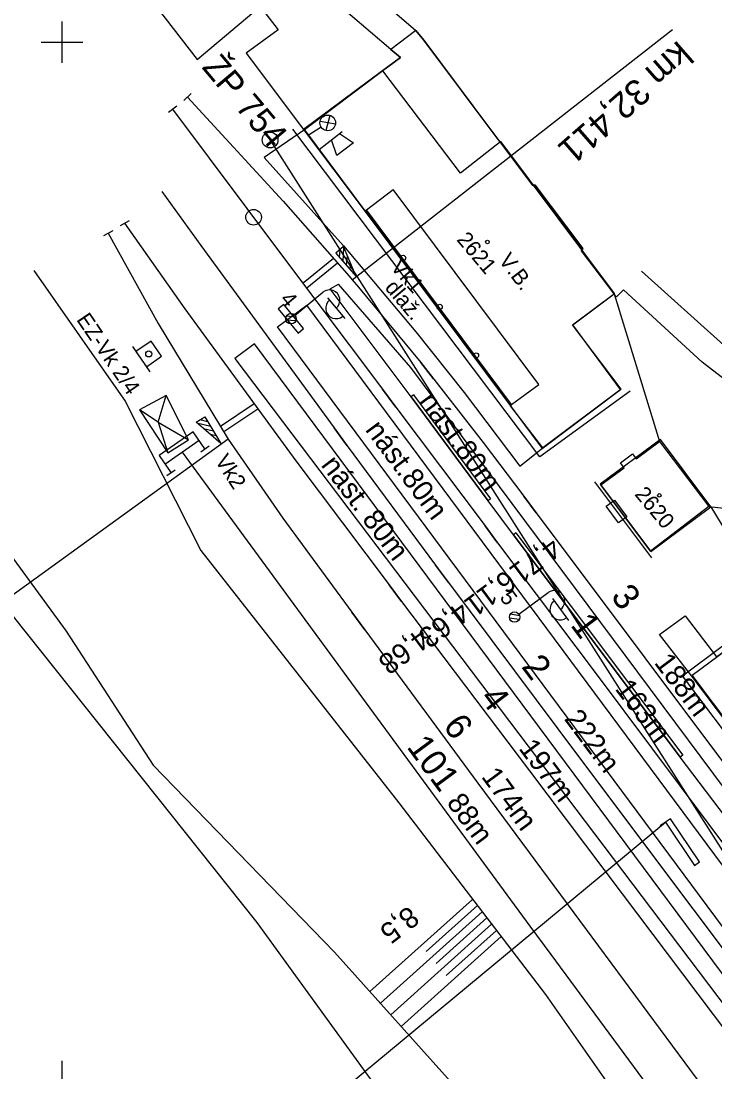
# Model space of a CAD drawing. Extents: x -804166 to -803706, y -1151030 to -1150147.
# Drawn here: x -804103.9 to -804037.2, y -1150299.1 to -1150198 of the extents above; entities that cross this region are included whole.
import ezdxf

# ---------------------------------------------------------------- set-up
doc = ezdxf.new("R2010")
doc.units = 0
for name, color, linetype in [('0381KM032-037P - Vrstva 1', 7, 'Continuous'), ('0381KM032-037P - Vrstva 12', 7, 'Continuous'), ('0381KM032-037P - Vrstva 14', 7, 'Continuous'), ('0381KM032-037P - Vrstva 15', 7, 'Continuous'), ('0381KM032-037P - Vrstva 16', 7, 'Continuous'), ('0381KM032-037P - Vrstva 2', 7, 'Continuous'), ('0381KM032-037P - Vrstva 23', 7, 'Continuous'), ('0381KM032-037P - Vrstva 25', 7, 'Continuous'), ('0381KM032-037P - Vrstva 3', 7, 'Continuous'), ('0381KM032-037P - Vrstva 33', 7, 'Continuous'), ('0381KM032-037P - Vrstva 4', 7, 'Continuous'), ('0381KM032-037P - Vrstva 48', 7, 'Continuous'), ('0381KM032-037P - Vrstva 49', 7, 'Continuous'), ('0381KM032-037P - Vrstva 51', 7, 'Continuous'), ('0381KM032-037P - Vrstva 55', 7, 'Continuous'), ('0381KM032-037P - Vrstva 57', 7, 'Continuous'), ('0381KM032-037P - Vrstva 59', 7, 'Continuous'), ('0381KM032-037P - Vrstva 7', 7, 'Continuous'), ('0381KM032-037P - Vrstva 9', 7, 'Continuous'), ('hran DP - hran DP', 7, 'Continuous'), ('krizky_1000 - Vrstva 1', 7, 'Continuous'), ('vyt_sit - polygon', 7, 'Continuous'), ('vyt_sit - stávající', 7, 'Continuous')]:
    doc.layers.add(name, color=color, linetype=linetype)

msp = doc.modelspace()

# ---------------------------------------------------------------- linework, layer by layer
at = {"layer": '0381KM032-037P - Vrstva 1'}
for points in [[(-804087.93, -1150205.28), (-804078.71, -1150215.28), (-804072.37, -1150222.52), (-804072.08, -1150222.85), (-804071.47, -1150223.58), (-804065.48, -1150230.82), (-804059.47, -1150238.51), (-804055.55, -1150243.68), (-804054.36, -1150245.27), (-804043.89, -1150259.22), (-804035.37, -1150270.61), (-804034.4, -1150271.93), (-804017.97, -1150293.92), (-804002.6, -1150314.46), (-803985.38, -1150337.43), (-803955.87, -1150376.72)], [(-804089.35, -1150206.44), (-804078.67, -1150220.7), (-804069.15, -1150233.38), (-804067.86, -1150235.11), (-804059.28, -1150246.53), (-804058.07, -1150248.16), (-804048.7, -1150260.65), (-804037.85, -1150275.13), (-804021.63, -1150296.76), (-804006.14, -1150317.34), (-803988.98, -1150340.29), (-803981.9, -1150349.73)], [(-804090.39, -1150214.38), (-804086.65, -1150219.55), (-804073.82, -1150237.11), (-804072.56, -1150238.83), (-804064.05, -1150250.31), (-804062.81, -1150251.97), (-804052.29, -1150266.05), (-804042.5, -1150279.11), (-804026.55, -1150300.33), (-804011.27, -1150320.63), (-803993.37, -1150344.49), (-803965.17, -1150382.07), (-803953.84, -1150397.19)], [(-804093.97, -1150217.42), (-804088.17, -1150225.67), (-804077.51, -1150240.28), (-804068.52, -1150252.21), (-804067.31, -1150253.81), (-804055.01, -1150270.12), (-804046.09, -1150281.93), (-804030.05, -1150303.21), (-804014.76, -1150323.52), (-803996.92, -1150347.35), (-803968.88, -1150385.42), (-803942.6, -1150419.03)], [(-804095.55, -1150218.38), (-804090.74, -1150227.08), (-804084.01, -1150238.21), (-804078.76, -1150245.78), (-804072.11, -1150254.85), (-804070.85, -1150256.55), (-804059.97, -1150271.29), (-804049.56, -1150285.37), (-804034.13, -1150306.22), (-804018.79, -1150326.86), (-804001.18, -1150350.63), (-803980.37, -1150378.68), (-803972.82, -1150388.42), (-803965.21, -1150397.6)], [(-804088.45, -1150239.45), (-804070.36, -1150264.07), (-804054.98, -1150285.05), (-804052.95, -1150287.79), (-804037.56, -1150308.64), (-804021.87, -1150329.91), (-804004.48, -1150353.56), (-803990.76, -1150372.09)]]:
    msp.add_lwpolyline(points, dxfattribs=at)
at = {"layer": '0381KM032-037P - Vrstva 12'}
for p, q in [((-804066.16, -1150233.94), (-804066.4, -1150234.12)), ((-804066.16, -1150233.94), (-804058.75, -1150243.94)), ((-804066.4, -1150234.12), (-804058.99, -1150244.12)), ((-804058.75, -1150243.94), (-804058.99, -1150244.12)), ((-804056.32, -1150247.21), (-804056.56, -1150247.39)), ((-804056.56, -1150247.39), (-804040.5, -1150268.78)), ((-804056.32, -1150247.21), (-804040.26, -1150268.6)), ((-804040.26, -1150268.6), (-804040.5, -1150268.78))]:
    msp.add_line(p, q, dxfattribs=at)
at = {"layer": '0381KM032-037P - Vrstva 14'}
for p, q in [((-804074.2, -1150223.73), (-804073.38, -1150223.27)), ((-804079.27, -1150227.4), (-804076.45, -1150225.31)), ((-804028.77, -1150289.52), (-804076.45, -1150225.31)), ((-804031.59, -1150291.62), (-804079.27, -1150227.4)), ((-804081.46, -1150229.02), (-804083.37, -1150230.42)), ((-804033.77, -1150293.24), (-804081.46, -1150229.02)), ((-804083.37, -1150230.42), (-804035.09, -1150294.23))]:
    msp.add_line(p, q, dxfattribs=at)
for points in [[(-804026.2, -1150287.61), (-804040.5, -1150268.78), (-804056.56, -1150247.39), (-804058.99, -1150244.12), (-804066.4, -1150234.12), (-804074.2, -1150223.73)], [(-804025.08, -1150286.79), (-804066.44, -1150231.31), (-804073.38, -1150223.27)]]:
    msp.add_lwpolyline(points, dxfattribs=at)
at = {"layer": '0381KM032-037P - Vrstva 15'}
for p, q in [((-804090.09, -1150240.6), (-804086.81, -1150238.3)), ((-804086.65, -1150239.41), (-804085.83, -1150238.83)), ((-804089.92, -1150241.7), (-804089.1, -1150241.13))]:
    msp.add_line(p, q, dxfattribs=at)
msp.add_lwpolyline([(-804086.24, -1150239.12), (-804087.39, -1150237.48), (-804090.66, -1150239.78), (-804089.51, -1150241.41)], dxfattribs=at)
at = {"layer": '0381KM032-037P - Vrstva 16'}
msp.add_lwpolyline([(-804076.66, -1150208.44), (-804080.54, -1150211.1), (-804072.9, -1150219.59), (-804065.93, -1150227.88), (-804061.29, -1150233.69), (-804055.95, -1150240.78), (-804053.73, -1150239.04)], dxfattribs=at)
at = {"layer": '0381KM032-037P - Vrstva 2'}
for p, q in [((-804087.56, -1150204.95), (-804088.29, -1150205.62)), ((-804088.95, -1150206.14), (-804089.74, -1150206.75)), ((-804093.53, -1150217.18), (-804094.41, -1150217.66)), ((-804095.11, -1150218.14), (-804095.99, -1150218.62))]:
    msp.add_line(p, q, dxfattribs=at)
at = {"layer": '0381KM032-037P - Vrstva 23'}
for p, q in [((-804069.12, -1150202.75), (-804076.66, -1150208.44)), ((-804061.66, -1150212.61), (-804069.12, -1150202.75)), ((-804076.66, -1150208.44), (-804070.85, -1150216.23)), ((-804057.75, -1150209.57), (-804061.66, -1150212.61)), ((-804046.83, -1150224.17), (-804057.75, -1150209.57)), ((-804054.58, -1150213.81), (-804054.46, -1150213.73)), ((-804049.85, -1150219.86), (-804054.46, -1150213.73)), ((-804070.68, -1150216.13), (-804068.14, -1150214.18)), ((-804054.1, -1150232.95), (-804068.14, -1150214.18)), ((-804056.83, -1150234.94), (-804070.74, -1150216.16)), ((-804056.73, -1150234.87), (-804070.68, -1150216.13)), ((-804049.98, -1150219.96), (-804049.85, -1150219.86)), ((-804050.87, -1150227.2), (-804046.83, -1150224.17)), ((-804046.17, -1150233.38), (-804050.87, -1150227.2)), ((-804056.73, -1150234.87), (-804054.1, -1150232.95)), ((-804046.17, -1150233.38), (-804053.73, -1150239.04)), ((-804056.73, -1150234.87), (-804056.83, -1150234.98)), ((-804053.73, -1150239.04), (-804056.83, -1150234.98)), ((-804042.4, -1150238.22), (-804048.19, -1150242.52)), ((-804037.56, -1150244.69), (-804042.4, -1150238.22)), ((-804048.75, -1150242.29), (-804043.27, -1150249.62))]:
    msp.add_line(p, q, dxfattribs=at)
for points in [[(-804045.33, -1150233.58), (-804054, -1150239.88), (-804077.77, -1150208.37)], [(-804070.85, -1150216.23), (-804070.85, -1150216.23), (-804070.74, -1150216.16), (-804070.68, -1150216.13)], [(-804048.19, -1150242.52), (-804043.32, -1150249.01), (-804037.56, -1150244.69)], [(-804034.08, -1150269.19), (-804040.27, -1150260.96), (-804032.39, -1150255.05)], [(-804039.34, -1150260.91), (-804032.82, -1150256.05), (-804026.77, -1150264.06)], [(-804026.77, -1150264.06), (-804033.29, -1150268.94), (-804039.34, -1150260.91)]]:
    msp.add_lwpolyline(points, dxfattribs=at)
msp.add_lwpolyline([(-804078.65, -1150225.24), (-804079.18, -1150225.67), (-804077.27, -1150227.98), (-804076.75, -1150227.55)], close=True, dxfattribs=at)
for centre in [(-804067.18, -1150220.75), (-804063.65, -1150225.47), (-804060.15, -1150230.14)]:
    msp.add_circle(centre, 0.25, dxfattribs=at)
at = {"layer": '0381KM032-037P - Vrstva 25'}
for p, q in [((-804073.67, -1150207.9), (-804075.16, -1150207.64)), ((-804074.21, -1150207.04), (-804074.61, -1150208.49)), ((-804075.05, -1150208.17), (-804076.31, -1150208.99)), ((-804077.58, -1150226.29), (-804074.89, -1150224.06)), ((-804074.44, -1150224.59), (-804072.78, -1150226.6)), ((-804078.45, -1150226.7), (-804077.5, -1150226.79)), ((-804078.38, -1150226.33), (-804077.51, -1150226.42)), ((-804056.03, -1150255.02), (-804053.2, -1150252.96)), ((-804052.79, -1150253.53), (-804051.26, -1150255.63)), ((-804056.84, -1150255.01), (-804055.97, -1150255.15)), ((-804056.93, -1150255.37), (-804055.99, -1150255.52))]:
    msp.add_line(p, q, dxfattribs=at)
msp.add_lwpolyline([(-804047.64, -1150244.64), (-804046.84, -1150244.05), (-804045.65, -1150245.66), (-804046.45, -1150246.25), (-804047.64, -1150244.64)], dxfattribs=at)
for centre, radius in [((-804074.42, -1150207.76), 0.754), ((-804077.96, -1150226.61), 0.5), ((-804077.96, -1150226.61), 0.5), ((-804056.44, -1150255.31), 0.5), ((-804056.44, -1150255.31), 0.5)]:
    msp.add_circle(centre, radius, dxfattribs=at)
for centre, start, end in [((-804074.25, -1150224.83), 309.662, 129.662), ((-804073.62, -1150225.6), 128.9595, 310.3646), ((-804052.61, -1150253.77), 305.995, 125.995), ((-804052.04, -1150254.59), 125.2924, 306.6976)]:
    msp.add_arc(centre, 1, start, end, dxfattribs=at)
at = {"layer": '0381KM032-037P - Vrstva 3'}
for p, q in [((-804072.08, -1150222.85), (-804041.24, -1150198.77)), ((-804072.95, -1150221.1), (-804072.86, -1150219.76)), ((-804073.64, -1150220.31), (-804073.63, -1150220.3)), ((-804073.3, -1150220.7), (-804073.23, -1150219.95)), ((-804072.61, -1150221.49), (-804072.53, -1150220.52)), ((-804072.26, -1150221.89), (-804072.22, -1150221.27)), ((-804071.91, -1150222.28), (-804071.9, -1150222.04)), ((-804091.42, -1150228.76), (-804092.88, -1150229.76)), ((-804090.42, -1150230.22), (-804091.42, -1150228.76)), ((-804093.21, -1150229.27), (-804091.55, -1150231.71)), ((-804092.88, -1150229.76), (-804091.88, -1150231.22)), ((-804091.88, -1150231.22), (-804090.42, -1150230.22)), ((-804085.69, -1150236.97), (-804087.02, -1150236.65)), ((-804085.97, -1150236.52), (-804086.71, -1150236.34)), ((-804086.24, -1150236.07), (-804086.26, -1150236.06)), ((-804085.42, -1150237.43), (-804086.38, -1150237.19)), ((-804085.14, -1150237.88), (-804085.74, -1150237.73)), ((-804084.01, -1150238.21), (-804117.81, -1150262.63)), ((-804084.87, -1150238.33), (-804085.1, -1150238.28))]:
    msp.add_line(p, q, dxfattribs=at)
for points in [[(-804071.7, -1150222.53), (-804072.9, -1150219.66), (-804073.64, -1150220.31), (-804071.7, -1150222.53)], [(-804084.7, -1150238.62), (-804087.1, -1150236.57), (-804086.25, -1150236.06), (-804084.7, -1150238.62)]]:
    msp.add_lwpolyline(points, dxfattribs=at)
msp.add_circle((-804091.65, -1150229.99), 0.296, dxfattribs=at)
at = {"layer": '0381KM032-037P - Vrstva 33'}
msp.add_line((-804075.25, -1150210.32), (-804073.04, -1150208.6), dxfattribs=at)
msp.add_lwpolyline([(-804073.28, -1150208.79), (-804071.96, -1150209.67), (-804073.54, -1150210.89), (-804074.07, -1150209.4)], dxfattribs=at)
at = {"layer": '0381KM032-037P - Vrstva 4'}
for p, q in [((-804064.23, -1150232.38), (-804065.48, -1150230.82)), ((-804067.86, -1150235.11), (-804069.15, -1150233.38)), ((-804072.56, -1150238.83), (-804073.82, -1150237.11)), ((-804054.36, -1150245.27), (-804055.55, -1150243.68)), ((-804058.07, -1150248.16), (-804059.28, -1150246.53)), ((-804062.81, -1150251.97), (-804064.05, -1150250.31)), ((-804067.31, -1150253.81), (-804068.52, -1150252.21)), ((-804070.85, -1150256.55), (-804072.11, -1150254.85))]:
    msp.add_line(p, q, dxfattribs=at)
at = {"layer": '0381KM032-037P - Vrstva 48'}
for p, q in [((-804060.48, -1150282.47), (-804070.36, -1150291.35)), ((-804060.02, -1150283.07), (-804064.94, -1150287.49)), ((-804059.56, -1150283.67), (-804069.35, -1150292.46)), ((-804059.11, -1150284.26), (-804063.98, -1150288.64)), ((-804058.65, -1150284.86), (-804068.35, -1150293.58)), ((-804058.19, -1150285.46), (-804063.02, -1150289.8)), ((-804057.73, -1150286.05), (-804067.35, -1150294.7))]:
    msp.add_line(p, q, dxfattribs=at)
at = {"layer": '0381KM032-037P - Vrstva 49'}
for q in [(-804089.96, -1150233.98), (-804092.55, -1150235.38), (-804087.81, -1150238.25), (-804089.82, -1150239.52)]:
    msp.add_line((-804090.75, -1150236.55), q, dxfattribs=at)
for points in [[(-804102.72, -1150221.96), (-804093.91, -1150234.53), (-804086.64, -1150248.91), (-804067.58, -1150273.2)], [(-804119.6, -1150227.37), (-804114.18, -1150233.24), (-804110.61, -1150241.24), (-804107.35, -1150246.09), (-804099.61, -1150256.67), (-804091.21, -1150269.57), (-804073.78, -1150287.54), (-804061.47, -1150301.24), (-804053.54, -1150315.4), (-804051.02, -1150318.44), (-804043.41, -1150327.56), (-804036.34, -1150339.31), (-804033.47, -1150348.91), (-804032.83, -1150355.72)], [(-804089.82, -1150239.52), (-804087.81, -1150238.25), (-804089.96, -1150233.98), (-804092.55, -1150235.38), (-804089.82, -1150239.52)], [(-804067.58, -1150273.2), (-804053.47, -1150291.61), (-804044.04, -1150305.1), (-804036.58, -1150319.92), (-804030.41, -1150335.37), (-804026.23, -1150342.57), (-804022.74, -1150350.54)]]:
    msp.add_lwpolyline(points, dxfattribs=at)
at = {"layer": '0381KM032-037P - Vrstva 51'}
for points in [[(-804044.22, -1150222.03), (-804036.31, -1150229.15), (-804029.46, -1150234.23), (-804026.23, -1150236.21)], [(-804027.57, -1150238.43), (-804032.18, -1150235.55), (-804038.4, -1150230.77), (-804045.96, -1150223.83), (-804046.63, -1150224.5), (-804046.89, -1150224.2)], [(-804037.56, -1150244.69), (-804031.31, -1150254.99), (-804027.1, -1150261.05), (-804017.62, -1150257.21), (-804018.95, -1150253.97), (-804019.08, -1150250.33), (-804014.25, -1150251.35)]]:
    msp.add_lwpolyline(points, dxfattribs=at)
at = {"layer": '0381KM032-037P - Vrstva 55'}
for points in [[(-804076.76, -1150208.41), (-804070.92, -1150216.16), (-804056.87, -1150234.96), (-804053.79, -1150239.08), (-804046.26, -1150233.41), (-804050.84, -1150227.18), (-804046.86, -1150224.2), (-804050.01, -1150220.06), (-804049.93, -1150219.91), (-804054.58, -1150213.71), (-804054.7, -1150213.8), (-804057.84, -1150209.6), (-804058.02, -1150209.36), (-804065.16, -1150199.8), (-804065.96, -1150198.88), (-804068.34, -1150200.69), (-804067.42, -1150201.47), (-804069.26, -1150202.82)], [(-804048.13, -1150242.59), (-804045.9, -1150240.94), (-804046.26, -1150240.46), (-804045.09, -1150239.61), (-804044.74, -1150240.08), (-804042.5, -1150238.42), (-804037.73, -1150244.68), (-804043.35, -1150248.97)], [(-804042.49, -1150256.99), (-804040.01, -1150255.2), (-804037.01, -1150259.13), (-804032.83, -1150256.09), (-804033.46, -1150255.26), (-804032.63, -1150254.75), (-804027.25, -1150261.82), (-804028.04, -1150262.42), (-804026.84, -1150264.01), (-804033.36, -1150268.97), (-804039.39, -1150261.01)]]:
    msp.add_lwpolyline(points, close=True, dxfattribs=at)
at = {"layer": '0381KM032-037P - Vrstva 59'}
for centre in [(-804059.05, -1150219.22), (-804042.51, -1150243.6)]:
    msp.add_circle(centre, 0.175, dxfattribs=at)
at = {"layer": '0381KM032-037P - Vrstva 7'}
for p, q in [((-804073.87, -1150220.81), (-804076.8, -1150223.18)), ((-804073.48, -1150221.26), (-804076.44, -1150223.66)), ((-804081.49, -1150234.81), (-804084.75, -1150236.98)), ((-804081.14, -1150235.3), (-804084.44, -1150237.5))]:
    msp.add_line(p, q, dxfattribs=at)
msp.add_circle((-804081.56, -1150216.84), 0.75, dxfattribs=at)
at = {"layer": '0381KM032-037P - Vrstva 9'}
for p, q in [((-804041.91, -1150275.08), (-804093.56, -1150317.87)), ((-804041.93, -1150275.06), (-804042.43, -1150275.4)), ((-804041.43, -1150274.72), (-804041.93, -1150275.06)), ((-804041.93, -1150275.06), (-804039.13, -1150279.2)), ((-804038.63, -1150278.87), (-804041.43, -1150274.72)), ((-804039.13, -1150279.2), (-804038.63, -1150278.87))]:
    msp.add_line(p, q, dxfattribs=at)
at = {"layer": 'hran DP - hran DP'}
for p, q in [((-804068.34, -1150200.69), (-804079.56, -1150191.12)), ((-804094.06, -1150192.49), (-804087, -1150201.67)), ((-804087, -1150201.67), (-804080.94, -1150196.58)), ((-804080.94, -1150196.58), (-804079.2, -1150198.82)), ((-804079.2, -1150198.82), (-804082.27, -1150201.05)), ((-804065.96, -1150198.88), (-804065.16, -1150199.8)), ((-804065.16, -1150199.8), (-804058.84, -1150208.26)), ((-804082.27, -1150201.05), (-804076.76, -1150208.41)), ((-804069.26, -1150202.82), (-804067.42, -1150201.47)), ((-804067.42, -1150201.47), (-804068.34, -1150200.69)), ((-804076.76, -1150208.41), (-804069.26, -1150202.82)), ((-804058.84, -1150208.26), (-804054.7, -1150213.8)), ((-804054.7, -1150213.8), (-804054.58, -1150213.71)), ((-804054.58, -1150213.71), (-804049.93, -1150219.91)), ((-804049.93, -1150219.91), (-804050.01, -1150220.06)), ((-804050.01, -1150220.06), (-804046.86, -1150224.2)), ((-804046.86, -1150224.2), (-804042.5, -1150238.42)), ((-804081.21, -1150284.7), (-804121.35, -1150234.4)), ((-804042.5, -1150238.42), (-804037.73, -1150244.68)), ((-804037.73, -1150244.68), (-804020.87, -1150246.51)), ((-804060.01, -1150313.9), (-804081.21, -1150284.7))]:
    msp.add_line(p, q, dxfattribs=at)
msp.add_lwpolyline([(-804077.91, -1150189.15), (-804072.79, -1150192.97), (-804065.96, -1150198.88)], dxfattribs=at)
at = {"layer": 'krizky_1000 - Vrstva 1'}
for points in [[(-804100, -1150198), (-804100, -1150202)], [(-804102, -1150200), (-804098, -1150200)], [(-804100, -1150298), (-804100, -1150302)]]:
    msp.add_lwpolyline(points, dxfattribs=at)
at = {"layer": 'vyt_sit - polygon'}
msp.add_line((-804079.95, -1150209.42), (-804016.51, -1150309.12), dxfattribs=at)
at = {"layer": 'vyt_sit - stávající'}
msp.add_line((-804080.02, -1150209.41), (-804079.92, -1150209.41), dxfattribs=at)
msp.add_circle((-804079.97, -1150209.41), 0.756, dxfattribs=at)

# ---------------------------------------------------------------- texts
at = {"layer": '0381KM032-037P - Vrstva 1'}
for s, height, rotation, p in [('4,71', 2, 216.8648, (-804052.93, -1150247.54)), ('6,11', 2, 216.7727, (-804057.27, -1150250.69)), ('3', 2.5, 306.8758, (-804047.25, -1150253.34)), ('4,63', 2, 217.0219, (-804061.71, -1150253.7)), ('1', 2.5, 306.8648, (-804051.13, -1150256.1)), ('4,68', 2, 216.4419, (-804065.54, -1150256.27)), ('2', 2.5, 306.7727, (-804055.85, -1150260.09)), ('188m', 2, 306.8758, (-804043.07, -1150259.71)), ('163m', 2, 306.8648, (-804046.84, -1150262.22)), ('4', 2.5, 307.0782, (-804059.86, -1150263.12)), ('222m', 2, 306.7727, (-804051.73, -1150265.12)), ('6', 2.5, 306.4846, (-804063.4, -1150265.8)), ('101', 2.5, 306.4445, (-804066.89, -1150267.81)), ('197m', 2, 307.0782, (-804056.11, -1150267.96)), ('174m', 2, 306.4846, (-804059.71, -1150270.67)), ('88m', 2, 306.4445, (-804063.05, -1150273.18))]:
    msp.add_text(s, height=height, rotation=rotation, dxfattribs=at).set_placement(p)
at = {"layer": '0381KM032-037P - Vrstva 14'}
for s, rotation, p in [('nást.80m', 306.522, (-804065.75, -1150234.58)), ('nást.80m', 306.5941, (-804070.88, -1150237.3)), ('nást. 80m', 307.1095, (-804075.14, -1150240.7))]:
    msp.add_text(s, height=2, rotation=rotation, dxfattribs=at).set_placement(p)
at = {"layer": '0381KM032-037P - Vrstva 16'}
msp.add_text('dlaž.', height=1.5, rotation=310.0372, dxfattribs=at).set_placement((-804069, -1150223.65))
at = {"layer": '0381KM032-037P - Vrstva 23'}
msp.add_text('V.B.', height=1.5, rotation=307.1118, dxfattribs=at).set_placement((-804058.03, -1150221))
at = {"layer": '0381KM032-037P - Vrstva 25'}
for s, rotation, p in [('4', 309.662, (-804079.09, -1150224.78)), ('5', 305.995, (-804057.93, -1150253.43))]:
    msp.add_text(s, height=1.5, rotation=rotation, dxfattribs=at).set_placement(p)
at = {"layer": '0381KM032-037P - Vrstva 3'}
for s, height, rotation, p in [('km 32,411', 2.5, 221.1865, (-804040.7, -1150199.75)), ('Vk1', 1.5, 311.1865, (-804068.46, -1150221.68)), ('EZ-Vk 2/4', 1.5, 304.3062, (-804098.66, -1150226.7)), ('Vk2', 1.5, 302.561, (-804085.32, -1150240.25))]:
    msp.add_text(s, height=height, rotation=rotation, dxfattribs=at).set_placement(p)
at = {"layer": '0381KM032-037P - Vrstva 48'}
msp.add_text('8,5', height=2, rotation=217.4721, dxfattribs=at).set_placement((-804066.63, -1150283.02))
at = {"layer": '0381KM032-037P - Vrstva 57'}
for s, rotation, p in [('2621', 310.0368, (-804062.08, -1150219.03)), ('2620', 309.9614, (-804044.95, -1150243.53))]:
    msp.add_text(s, height=1.5, rotation=rotation, dxfattribs=at).set_placement(p)
at = {"layer": 'vyt_sit - stávající'}
msp.add_text('ŽP 754', height=2.4, rotation=310, dxfattribs=at).set_placement((-804086.61, -1150202.44))

doc.saveas('drawing.dxf')
